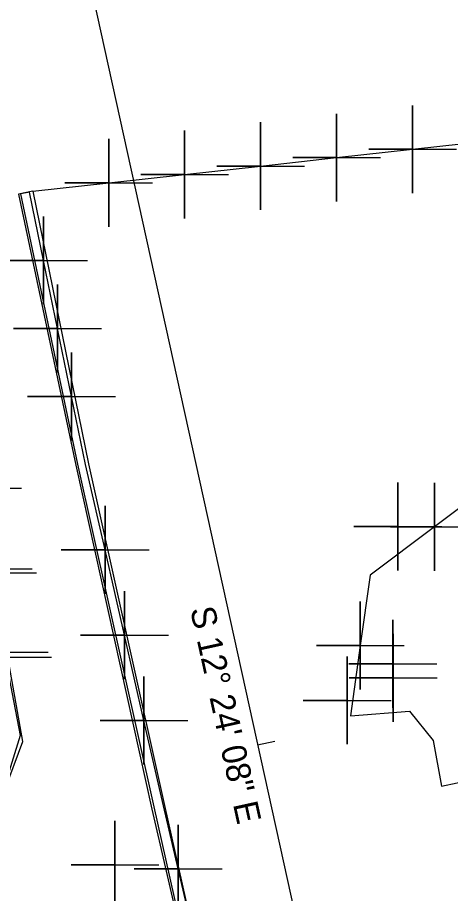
# Model space of a CAD drawing. Extents: x 2260968 to 2264340, y 653057 to 655850.
# Drawn here: x 2261662.09 to 2261686.71, y 655124.13 to 655173.96 of the extents above; entities that cross this region are included whole.
import ezdxf

# ---------------------------------------------------------------- set-up
doc = ezdxf.new("R2010")
doc.units = 0
for name, color, linetype in [('CL_X_Construction', 7, 'Continuous'), ('Default', 7, 'Continuous'), ('GE_X_CL_10', 7, 'Continuous')]:
    doc.layers.add(name, color=color, linetype=linetype)

msp = doc.modelspace()

# ---------------------------------------------------------------- linework, layer by layer
at = {"layer": 'CL_X_Construction'}
msp.add_line((2261663.661, 655187.525), (2261687.579, 655078.757), dxfattribs=at)
msp.add_line((2261663.661, 655187.525), (2261687.579, 655078.757), dxfattribs=at)
at = {"layer": 'Default'}
for points in [[(2261684.554, 655166.467), (2261684.554, 655168.967), (2261684.554, 655166.467), (2261682.054, 655166.467), (2261684.554, 655166.467), (2261684.554, 655163.967), (2261684.554, 655166.467), (2261687.054, 655166.467)], [(2261680.233, 655165.992), (2261680.233, 655168.492), (2261680.233, 655165.992), (2261677.733, 655165.992), (2261680.233, 655165.992), (2261680.233, 655163.492), (2261680.233, 655165.992), (2261682.733, 655165.992)], [(2261675.911, 655165.516), (2261675.911, 655168.016), (2261675.911, 655165.516), (2261673.411, 655165.516), (2261675.911, 655165.516), (2261675.911, 655163.016), (2261675.911, 655165.516), (2261678.411, 655165.516)], [(2261671.59, 655165.04), (2261671.59, 655167.54), (2261671.59, 655165.04), (2261669.09, 655165.04), (2261671.59, 655165.04), (2261671.59, 655162.54), (2261671.59, 655165.04), (2261674.09, 655165.04)], [(2261662.947, 655164.088), (2261667.269, 655164.564), (2261671.59, 655165.04), (2261675.911, 655165.516), (2261680.233, 655165.992), (2261684.554, 655166.467), (2261688.876, 655166.943)], [(2261667.269, 655164.564), (2261667.269, 655167.064), (2261667.269, 655164.564), (2261664.769, 655164.564), (2261667.269, 655164.564), (2261667.269, 655162.064), (2261667.269, 655164.564), (2261669.769, 655164.564)], [(2261662.947, 655164.088), (2261662.15, 655163.916), (2261665.409, 655148.49), (2261669.725, 655128.935), (2261671.359, 655121.881), (2261676.313, 655098.403), (2261676.856, 655098.414), (2261687.079, 655100.295), (2261698.415, 655102.238), (2261698.232, 655103.328)], [(2261698.117, 655103.117), (2261694.38, 655102.498), (2261690.643, 655101.879), (2261686.906, 655101.26), (2261683.582, 655100.637), (2261680.258, 655100.013), (2261676.934, 655099.389), (2261676.827, 655099.357), (2261675.795, 655104.245), (2261674.763, 655109.133), (2261673.731, 655114.022), (2261672.699, 655118.91), (2261672.048, 655121.962), (2261671.216, 655125.544), (2261670.383, 655129.125), (2261669.277, 655133.976), (2261668.171, 655138.827), (2261667.065, 655143.678), (2261665.959, 655148.529), (2261665.16, 655152.403), (2261664.361, 655156.276), (2261663.561, 655160.15), (2261662.762, 655164.023), (2261662.283, 655163.935)], [(2261698.208, 655102.439), (2261687.037, 655100.422), (2261677.069, 655098.485), (2261676.401, 655098.448), (2261672.065, 655118.81), (2261671.466, 655121.882), (2261669.864, 655129.058), (2261665.507, 655148.548), (2261662.283, 655163.935)], [(2261662.947, 655164.088), (2261666.116, 655148.584), (2261670.439, 655129.14), (2261672.036, 655122.054), (2261672.783, 655119.01), (2261676.885, 655099.519), (2261686.86, 655101.353), (2261698.232, 655103.328)], [(2261663.561, 655160.15), (2261663.561, 655162.65), (2261663.561, 655160.15), (2261661.061, 655160.15), (2261663.561, 655160.15), (2261663.561, 655157.65), (2261663.561, 655160.15), (2261666.061, 655160.15)], [(2261664.361, 655156.276), (2261664.361, 655158.776), (2261664.361, 655156.276), (2261661.861, 655156.276), (2261664.361, 655156.276), (2261664.361, 655153.776), (2261664.361, 655156.276), (2261666.861, 655156.276)], [(2261665.16, 655152.403), (2261665.16, 655154.903), (2261665.16, 655152.403), (2261662.66, 655152.403), (2261665.16, 655152.403), (2261665.16, 655149.903), (2261665.16, 655152.403), (2261667.66, 655152.403)], [(2261738.811, 655147.864), (2261734.819, 655150.063), (2261730.828, 655152.261), (2261726.994, 655152.32), (2261723.161, 655152.378), (2261718.825, 655151.744), (2261714.49, 655151.11), (2261710.154, 655150.475), (2261705.819, 655149.841), (2261701.755, 655149.363), (2261697.691, 655148.885), (2261692.995, 655148.31), (2261692.701, 655148.263), (2261689.464, 655147.743), (2261685.802, 655144.989), (2261682.14, 655142.235), (2261681.579, 655138.236), (2261681.018, 655134.236), (2261684.376, 655134.5), (2261685.727, 655132.842), (2261686.199, 655130.24), (2261688.865, 655130.81), (2261691.785, 655131.028)], [(2261659.803, 655147.186), (2261659.803, 655149.686), (2261659.803, 655147.186), (2261657.303, 655147.186), (2261659.803, 655147.186), (2261659.803, 655144.686), (2261659.803, 655147.186), (2261662.303, 655147.186)], [(2261683.708, 655145.012), (2261683.708, 655147.512), (2261683.708, 655145.012), (2261681.208, 655145.012), (2261683.708, 655145.012), (2261683.708, 655142.512), (2261683.708, 655145.012), (2261686.208, 655145.012)], [(2261685.802, 655144.989), (2261685.802, 655147.489), (2261685.802, 655144.989), (2261683.302, 655144.989), (2261685.802, 655144.989), (2261685.802, 655142.489), (2261685.802, 655144.989), (2261688.302, 655144.989)], [(2261667.065, 655143.678), (2261667.065, 655146.178), (2261667.065, 655143.678), (2261664.565, 655143.678), (2261667.065, 655143.678), (2261667.065, 655141.178), (2261667.065, 655143.678), (2261669.565, 655143.678)], [(2261660.424, 655142.597), (2261660.424, 655145.097), (2261660.424, 655142.597), (2261657.924, 655142.597), (2261660.424, 655142.597), (2261660.424, 655140.097), (2261660.424, 655142.597), (2261662.924, 655142.597)], [(2261660.665, 655142.382), (2261660.665, 655144.882), (2261660.665, 655142.382), (2261658.165, 655142.382), (2261660.665, 655142.382), (2261660.665, 655139.882), (2261660.665, 655142.382), (2261663.165, 655142.382)], [(2261668.171, 655138.827), (2261668.171, 655141.327), (2261668.171, 655138.827), (2261665.671, 655138.827), (2261668.171, 655138.827), (2261668.171, 655136.327), (2261668.171, 655138.827), (2261670.671, 655138.827)], [(2261681.579, 655138.236), (2261681.579, 655140.736), (2261681.579, 655138.236), (2261679.079, 655138.236), (2261681.579, 655138.236), (2261681.579, 655135.736), (2261681.579, 655138.236), (2261684.079, 655138.236)], [(2261661.335, 655137.855), (2261661.335, 655140.355), (2261661.335, 655137.855), (2261658.835, 655137.855), (2261661.335, 655137.855), (2261661.335, 655135.355), (2261661.335, 655137.855), (2261663.835, 655137.855)], [(2261661.527, 655137.578), (2261661.527, 655140.078), (2261661.527, 655137.578), (2261659.027, 655137.578), (2261661.527, 655137.578), (2261661.527, 655135.078), (2261661.527, 655137.578), (2261664.027, 655137.578)], [(2261683.432, 655137.192), (2261683.432, 655139.692), (2261683.432, 655137.192), (2261680.932, 655137.192), (2261683.432, 655137.192), (2261683.432, 655134.692), (2261683.432, 655137.192), (2261685.932, 655137.192)], [(2261683.443, 655136.402), (2261683.443, 655138.902), (2261683.443, 655136.402), (2261680.943, 655136.402), (2261683.443, 655136.402), (2261683.443, 655133.902), (2261683.443, 655136.402), (2261685.943, 655136.402)], [(2261661.335, 655137.855), (2261662.245, 655133.112), (2261661.295, 655130.043)], [(2261661.337, 655129.969), (2261662.389, 655132.774), (2261661.527, 655137.578)], [(2261680.834, 655135.119), (2261680.834, 655137.619), (2261680.834, 655135.119), (2261678.334, 655135.119), (2261680.834, 655135.119), (2261680.834, 655132.619), (2261680.834, 655135.119), (2261683.334, 655135.119)], [(2261669.277, 655133.976), (2261669.277, 655136.476), (2261669.277, 655133.976), (2261666.777, 655133.976), (2261669.277, 655133.976), (2261669.277, 655131.476), (2261669.277, 655133.976), (2261671.777, 655133.976)], [(2261667.627, 655125.762), (2261667.627, 655128.262), (2261667.627, 655125.762), (2261665.127, 655125.762), (2261667.627, 655125.762), (2261667.627, 655123.262), (2261667.627, 655125.762), (2261670.127, 655125.762)], [(2261671.216, 655125.544), (2261671.216, 655128.044), (2261671.216, 655125.544), (2261668.716, 655125.544), (2261671.216, 655125.544), (2261671.216, 655123.044), (2261671.216, 655125.544), (2261673.716, 655125.544)]]:
    msp.add_lwpolyline(points, dxfattribs=at)
at = {"layer": 'GE_X_CL_10'}
for p, q in [((2261663.661, 655187.525), (2261687.579, 655078.757)), ((2261675.741, 655132.59), (2261676.718, 655132.805)), ((2261675.741, 655132.59), (2261676.718, 655132.805))]:
    msp.add_line(p, q, dxfattribs=at)

# ---------------------------------------------------------------- texts
msp.add_text('S 12%%d 24\' 08" E', height=1.4, rotation=282.4021, dxfattribs=at).set_placement((2261671.895, 655140.301))

doc.saveas('drawing.dxf')
